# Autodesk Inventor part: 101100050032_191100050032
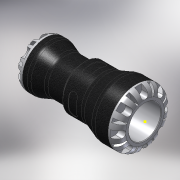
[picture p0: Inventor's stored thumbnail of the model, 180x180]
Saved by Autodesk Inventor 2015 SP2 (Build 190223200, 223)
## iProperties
Created: 2016-12
Part Number: 101100050032_191100050032
Material: PVC-Piping
Description: PLASSON REDUCING COUPLING 50X32 SERIES 1
Document SubType Name: Modeling
Designer: KIM
Mass: 416.404 g
Surface Area: 615.124 cm^2
Volume: 297.431 cm^3
Density: 1.4 g/cm^3
Appearance: Black Cast
Author: KIM
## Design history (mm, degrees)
derived "1011.ipt"
feature "Solid1::1011.ipt"
tag "TaggingFeature1"
body "Solid1"
other parameters: "d0" = 152, "d2" = 33.18, "d4" = 85, "d6" = 79, "d7" = 4.16667, "d8" = 58, "d9" = 32, "d11" = 23.1, "d12" = 55, "d13" = 2.66667, "d14" = 68, "d15" = 46.4, "d16" = 20 deg, "d17" = 20 deg, "d18" = 130 deg, "d26" = 0, "d28" = 360 deg, "d30" = 8 deg, "d31" = 1, "d32" = 8 deg, "d33" = 1, "d35" = 0, "d37" = 360 deg, "d39" = 7.2, "d42" = 7.2, "d43" = 0, "d45" = 360 deg, "d47" = 0.64, "d48" = 8 deg, "d49" = 8 deg, "d50" = 0.64, "d52" = 0, "d54" = 360 deg, "d56" = 11.6, "d57" = 17, "d58" = 0.5, "d60" = 10.2, "d61" = 12.5, "d62" = 16.2, "d63" = 0, "d66" = 0, "d68" = 360 deg, "d75" = 9.58673, "d77" = 66.3, "d78" = 0.85, "d1" = 32, "E_" = 85, "H_" = 152, "l_" = 79, "E1" = 58, "l1" = 55, "Plasson" = 1, "d20" = 9, "d21" = 12.5, "d23" = 85, "d40" = 58, "d59" = 19.17345
